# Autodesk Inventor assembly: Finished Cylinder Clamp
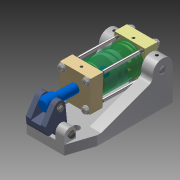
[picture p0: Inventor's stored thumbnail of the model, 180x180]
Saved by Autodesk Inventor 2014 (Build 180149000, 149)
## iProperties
Created: 2008-07
Part Number: Finished Cylinder Clamp
Document SubType Name: Assembly
Designer: normanpa
Author: normanpa
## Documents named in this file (9)
- C:\Users\iTools\Desktop\tutorial files\Cylinder Clamp\Cylinder Clamp.iam
- C:\Users\iTools\Desktop\tutorial files\Cylinder Clamp\Cylinder Base.ipt
- C:\Users\iTools\Desktop\tutorial files\Cylinder Clamp\Clamp.ipt
- C:\Users\iTools\Desktop\tutorial files\Cylinder Clamp\Long Shaft.ipt
- C:\Users\iTools\Desktop\tutorial files\Cylinder Clamp\Short Shaft.ipt
- C:\Users\iTools\Desktop\tutorial files\Cylinder Clamp\Lock Pin.ipt
- C:\Users\iTools\Desktop\tutorial files\Cylinder Clamp\6mm SHCS.ipt
- C:\Users\iTools\Desktop\tutorial files\Cylinder Clamp\ANSI B 27.7M - 3AMI-7.ipt
- C:\Users\iTools\Desktop\tutorial files\Cylinder Clamp\Cylinder Body Sub_Assy.iam
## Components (13 placed, 8 different names)
1. Cylinder Base:1 — Flush:1, Mate:1, Mate:5, Mate:7, Mate:8, Mate:9, Mate:10, Angle:1, Mate:11, Mate:12, Angle:2, Mate:15, Mate:16, Flush:2, Mate:17
2. Cylinder Body Sub_Assy:1 [sub-assembly] — Flush:2, Mate:17, Mate:18
3. Clamp:1 — Flush:1, Mate:1, Mate:6
4. Long Shaft:1 — Mate:7, Mate:8, Insert:2, Insert:4
5. Short Shaft:1 — Mate:5, Mate:6, Mate:18, Insert:1, Insert:3
6. Lock Pin:1 — Mate:9, Mate:10, Angle:1, Mate:13
7. Lock Pin:2 — Mate:11, Mate:12, Angle:2, Mate:14
8. 6mm SHCS:1 — Mate:14, Mate:16
9. 6mm SHCS:2 — Mate:13, Mate:15
10. ANSI B 27.7M 3AMI-7:1 — Insert:3
11. ANSI B 27.7M 3AMI-7:2 — Insert:4
12. ANSI B 27.7M 3AMI-7:3 — Insert:2
13. ANSI B 27.7M 3AMI-7:4 — Insert:1
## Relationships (23: Mate 15, Insert 4, Flush 2, Angle 2)
- Flush:1: Cylinder Base:1 ↔ Clamp:1
- Mate:1: Cylinder Base:1 ↔ Clamp:1
- Mate:5: Cylinder Base:1 ↔ Short Shaft:1
- Mate:6: Clamp:1 ↔ Short Shaft:1
- Mate:7: Cylinder Base:1 ↔ Long Shaft:1
- Mate:8: Cylinder Base:1 ↔ Long Shaft:1
- Mate:9: Cylinder Base:1 ↔ Lock Pin:1
- Mate:10: Cylinder Base:1 ↔ Lock Pin:1
- Angle:1: Cylinder Base:1 ↔ Lock Pin:1
- Mate:11: Cylinder Base:1 ↔ Lock Pin:2
- Mate:12: Cylinder Base:1 ↔ Lock Pin:2
- Angle:2: Cylinder Base:1 ↔ Lock Pin:2
- Mate:13: Lock Pin:1 ↔ 6mm SHCS:2
- Mate:14: Lock Pin:2 ↔ 6mm SHCS:1
- Mate:15: Cylinder Base:1 ↔ 6mm SHCS:2
- Mate:16: Cylinder Base:1 ↔ 6mm SHCS:1
- Flush:2: Cylinder Base:1 ↔ Cylinder Body Sub_Assy:1
- Mate:17: Cylinder Base:1 ↔ Cylinder Body Sub_Assy:1
- Mate:18: Cylinder Body Sub_Assy:1 ↔ Short Shaft:1
- Insert:1: Short Shaft:1 ↔ ANSI B 27.7M 3AMI-7:4
- Insert:2: Long Shaft:1 ↔ ANSI B 27.7M 3AMI-7:3
- Insert:3: Short Shaft:1 ↔ ANSI B 27.7M 3AMI-7:1
- Insert:4: Long Shaft:1 ↔ ANSI B 27.7M 3AMI-7:2
